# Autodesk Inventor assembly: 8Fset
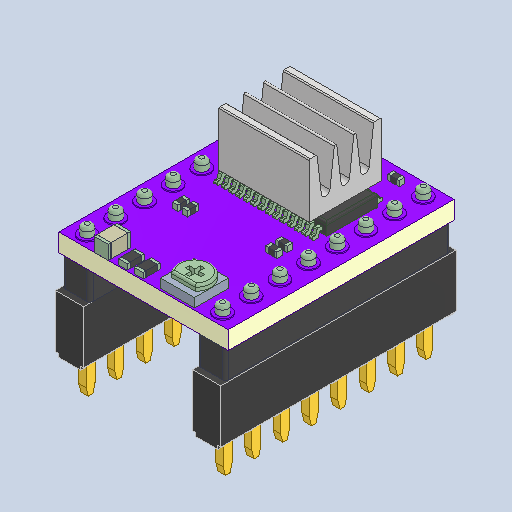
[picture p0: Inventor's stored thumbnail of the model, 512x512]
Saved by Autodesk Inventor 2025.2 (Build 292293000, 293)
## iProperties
Created: 2025-04
Part Number: 8Fset
Description: PART--DESC
Document SubType Name: Assembly
Designer: BennF
Author: BennF
Revision Number: NONE
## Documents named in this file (4)
- C:\Users\BennF\Nextcloud\Benutzer\CNC JarBeRi\existing parts\Electronics\RepRap A4988 Shied (USE WITHOUT ARDUINO)\reprap-a4988-1.snapshot.1\RepRap\RepRap\8Fset_1.iam
- C:\Users\BennF\Nextcloud\Benutzer\CNC JarBeRi\existing parts\Electronics\RepRap A4988 Shied (USE WITHOUT ARDUINO)\reprap-a4988-1.snapshot.1\RepRap\RepRap\8F_2.iam
- C:\Users\BennF\Nextcloud\Benutzer\CNC JarBeRi\existing parts\Electronics\RepRap A4988 Shied (USE WITHOUT ARDUINO)\reprap-a4988-1.snapshot.1\RepRap\RepRap\8F_3.iam
- C:\Users\BennF\Nextcloud\Benutzer\CNC JarBeRi\existing parts\Electronics\RepRap A4988 Shied (USE WITHOUT ARDUINO)\reprap-a4988-1.snapshot.1\RepRap\RepRap\DRV 8825_1.iam
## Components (3 placed, 2 different names)
1. 8F [sub-assembly]
2. 8F:1 [sub-assembly]
3. DRV 8825 [sub-assembly]
